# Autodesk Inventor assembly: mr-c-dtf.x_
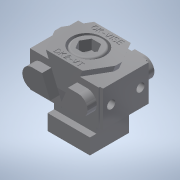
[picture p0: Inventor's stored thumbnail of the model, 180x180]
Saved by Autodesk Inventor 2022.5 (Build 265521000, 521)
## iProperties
Part Number: mr-c-dtf.x_
Material: 一般
Document SubType Name: Assembly
Designer: ImaoCorp
Sending System: SOLIDWORKS 2017-2017317
MC: AMD64
MC_MODEL: Intel64 Family 6 Model 60 Stepping 3, GenuineIntel
OS: Windows_NT
FRU: Parasolid Version 29.0, build 201,  4-17-2017
FORMAT: text
GUISE: transmit
KEY: mr-c-dtf
FILE: mr-c-dtf.x_t
DATE: Fri Jul 26 11:48:41 2019
Author: ImaoCorp
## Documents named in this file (5)
- X:\14_SW2022-Inv2022\00_全2023-1023新製品(TCC)まで\m\mr-c-dtf\MR-C-DTF.iam
- X:\14_SW2022-Inv2022\00_全2023-1023新製品(TCC)まで\m\mr-c-dtf\mr-c-dtf_01.ipt
- X:\14_SW2022-Inv2022\00_全2023-1023新製品(TCC)まで\m\mr-c-dtf\mr-c-dtf_02.ipt
- X:\14_SW2022-Inv2022\00_全2023-1023新製品(TCC)まで\m\mr-c-dtf\mr-c-dtf_03.ipt
- X:\14_SW2022-Inv2022\00_全2023-1023新製品(TCC)まで\m\mr-c-dtf\mr-c-dtf_04.ipt
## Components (4 placed, 4 different names)
1. mr-c-dtf_01
2. mr-c-dtf_02
3. mr-c-dtf_03
4. mr-c-dtf_04
